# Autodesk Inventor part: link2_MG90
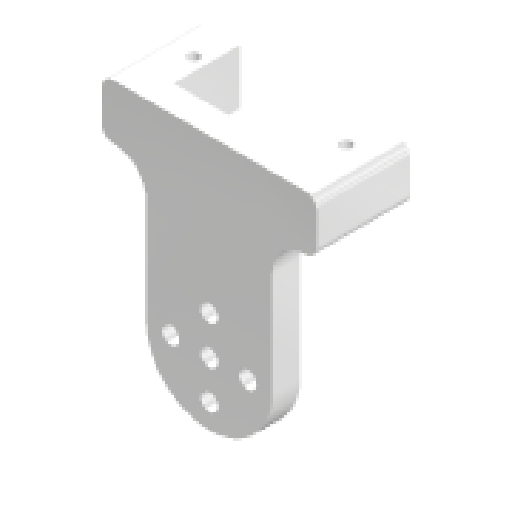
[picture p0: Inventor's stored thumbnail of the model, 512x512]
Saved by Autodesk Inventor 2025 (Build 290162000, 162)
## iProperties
Created: 2021-06
Part Number: link2_MG90
Material: Plastica ABS
Document SubType Name: Modeling
Designer: Ryzen5700u
Density: 1.06 g/cm^3
Appearance: Default
Author: Ryzen5700u
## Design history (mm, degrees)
feature "Solido1"
sketch "Schizzo1"
  geometry: C1 r 1.25 at (0, -7) reference; C2 r 1.25 at (-7, 0) reference; C3 r 1.25 at (0, 7) reference; C4 r 1.25 at (7, 0) reference; 5 further points
  constraints: 4 coincident
hole "Foro1" sketch "Schizzo1" at (0, -7), (-7, 0), (0, 7), (7, 0) diameter "d0" = 3.2; stored, may be unused: countersink angle "d4" = 89.9544 deg, drill point angle "d6" = 118 deg; dims "d1" = 6, "d2" = 11, "d3" = 2.6, "d5" = 8
node "Solido2"
